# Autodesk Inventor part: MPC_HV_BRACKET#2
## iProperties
Shininess: 64.0
Length Units: 11269
Angle Units: 11279
Time Units: 11290
Mass Units: 11283
Length Display Precision: 3
Angle Display Precision: 2
Compacted: True
Part Number: MPC_HV_BRACKET#2
Document SubType Name: Modeling
Created: 2004-08
Designer: John Blackburn
Manufacturer: Standard
Standards Organization: Custom
Material: Aluminum-6061
Density: 0.0
Volumn: 0.0
Area: 0.0
PropertySet Name: Model Information
Control State: 0
Master: False
Checked Out: False
Author: John Blackburn
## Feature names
1. Extrusion1
2. Chamfer1
3. Extrusion2
